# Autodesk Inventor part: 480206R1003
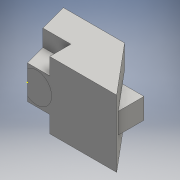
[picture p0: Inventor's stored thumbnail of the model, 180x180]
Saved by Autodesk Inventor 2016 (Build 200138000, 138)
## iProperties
Created: 2018-02
Part Number: 480206R1003
Material: 일반
Document SubType Name: Modeling
Designer: USER
Density: 1 g/cm^3
Appearance: 기본값
Author: USER
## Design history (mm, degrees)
sketch "스케치1"
  geometry: L1 (0, 0)-(80, 0); L2 (80, 0)-(43.08, 44); L3 (43.08, 44)-(-11.79, 44); L4 (-11.79, 44)-(0, 0)
  constraints: 8 end point, 1 horizontal, 1 parallel
  dimensions: "d0" = 80 distance of L1.start L1.end; "d1" = 50 deg angle of L1 L2; "d2" = 105 deg angle of L4 L3; "d4" = 44 distance between parallel lines of L1 L3
extrude "돌출1" new body sketch "스케치1" stored distance "d5" = 60; taper "d6" = 0 deg
sketch "스케치2"
  geometry: L1 (-11.79, 44)-(0, 0) reference; L2 (0, 0)-(80, 0) reference
sketch "스케치3"
  geometry: L1 (-11.79, 44)-(43.08, 44) reference; L2 (25.58, 44)-(28.795, 32); L3 (28.795, 32)-(53.149, 32); L4 (43.08, 44)-(80, 0) reference; 1 further point
  constraints: 4 end point, 2 point on line, 1 horizontal
  dimensions: "d9" = 75 deg angle of L3 L2; "d10" = 12 distance between parallel lines of L3 L1; "d11" = 17.5 distance of L2.start L1.end
extrude "돌출2" cut sketch "스케치3" stored distance "d12" = 18.5; taper "d13" = 0 deg
sketch "스케치4"
  geometry: L1 (43.08, 44)-(80, 0) reference; L2 (53.149, 32)-(28.795, 32) reference; L3 (53.149, 32)-(72.5, 32); L4 (72.5, 32)-(72.5, 8.938); 1 further point
  constraints: 4 end point, 1 horizontal, 1 perpendicular, 1 point on line
  dimensions: "d14" = 12 vertical distance of L3.end L1.start (derived); "d15" = 7.5 horizontal distance of L1.end L3.end
extrude "돌출3" join sketch "스케치4" stored distance "d16" = 18.5; taper "d17" = 0 deg
sketch "스케치5"
  geometry: 1 further point
sketch "스케치6"
  geometry: 1 further point
sketch "스케치7"
  geometry: L1 (-11.79, 44)-(0, 0) reference; L2 (-5.091, 19)-(20, 19); L3 (20, 19)-(20, 0); L4 (0, 0)-(80, 0) reference
  constraints: 4 end point, 2 point on line, 1 horizontal, 1 perpendicular
  dimensions: "d18" = 60 distance of L4.end L3.end; "d19" = 80 distance of L1.end L4.end (derived); "d20" = 19 distance between parallel lines of L4 L2
extrude "돌출4" cut sketch "스케치7" distance "d21" = 15; taper "d22" = 0 deg
sketch "스케치8"
  geometry: L1 (0, 0)-(54.869, 0) reference; L2 (0, 0)-(0, -60) reference; C1 r 5.5 at (20, -30); 1 further point
  constraints: 1 centre point
  dimensions: "d23" = 20 horizontal distance of C1.centre L1.start; "d24" = 11 diameter of C1; "d25" = 30 distance from line of C1.centre L1
extrude "돌출5" cut sketch "스케치8" distance "d26" = 30.5; taper "d27" = 0 deg
sketch "스케치9"
  geometry: L1 (60.462, 9.25)-(64.29, 9.25) reference; L2 (64.29, 9.25)-(64.29, -9.25) reference; L3 (64.29, -9.25)-(60.462, -9.25) reference; L4 (60.462, -9.25)-(60.462, -30) reference; L5 (60.462, -30)-(11.79, -30) reference; L6 (11.79, -30)-(11.79, -15) reference; L7 (11.79, -15)-(-11.828, -15) reference; L8 (-11.828, -15)-(-11.828, 15) reference; L9 (-11.828, 15)-(11.79, 15) reference; L10 (11.79, 15)-(11.79, 30) reference; L11 (11.79, 30)-(60.462, 30) reference; L12 (60.462, 30)-(60.462, 9.25) reference; L13 (-8.21, -15)-(-8.21, 15) reference; L14 (-8.21, 10.716)-(-8.21, -10.716); C1 r 5.5 at (0, 0) reference; A1 r 13.5 centre (0, 0) between (-8.21, -10.716) and (-8.21, 10.716); 1 further point
  constraints: 2 end point, 2 point on circle, 2 point on line, 1 centre point, 1 coincident, 1 collinear
  dimensions: "d28" = 27 diameter of A1
extrude "돌출6" new body sketch "스케치9" distance "d29" = 13.5; taper "d30" = 0 deg
node "솔리드1"
mirror "대칭1"
node "솔리드2"
node "절단 모서리 투영1"
